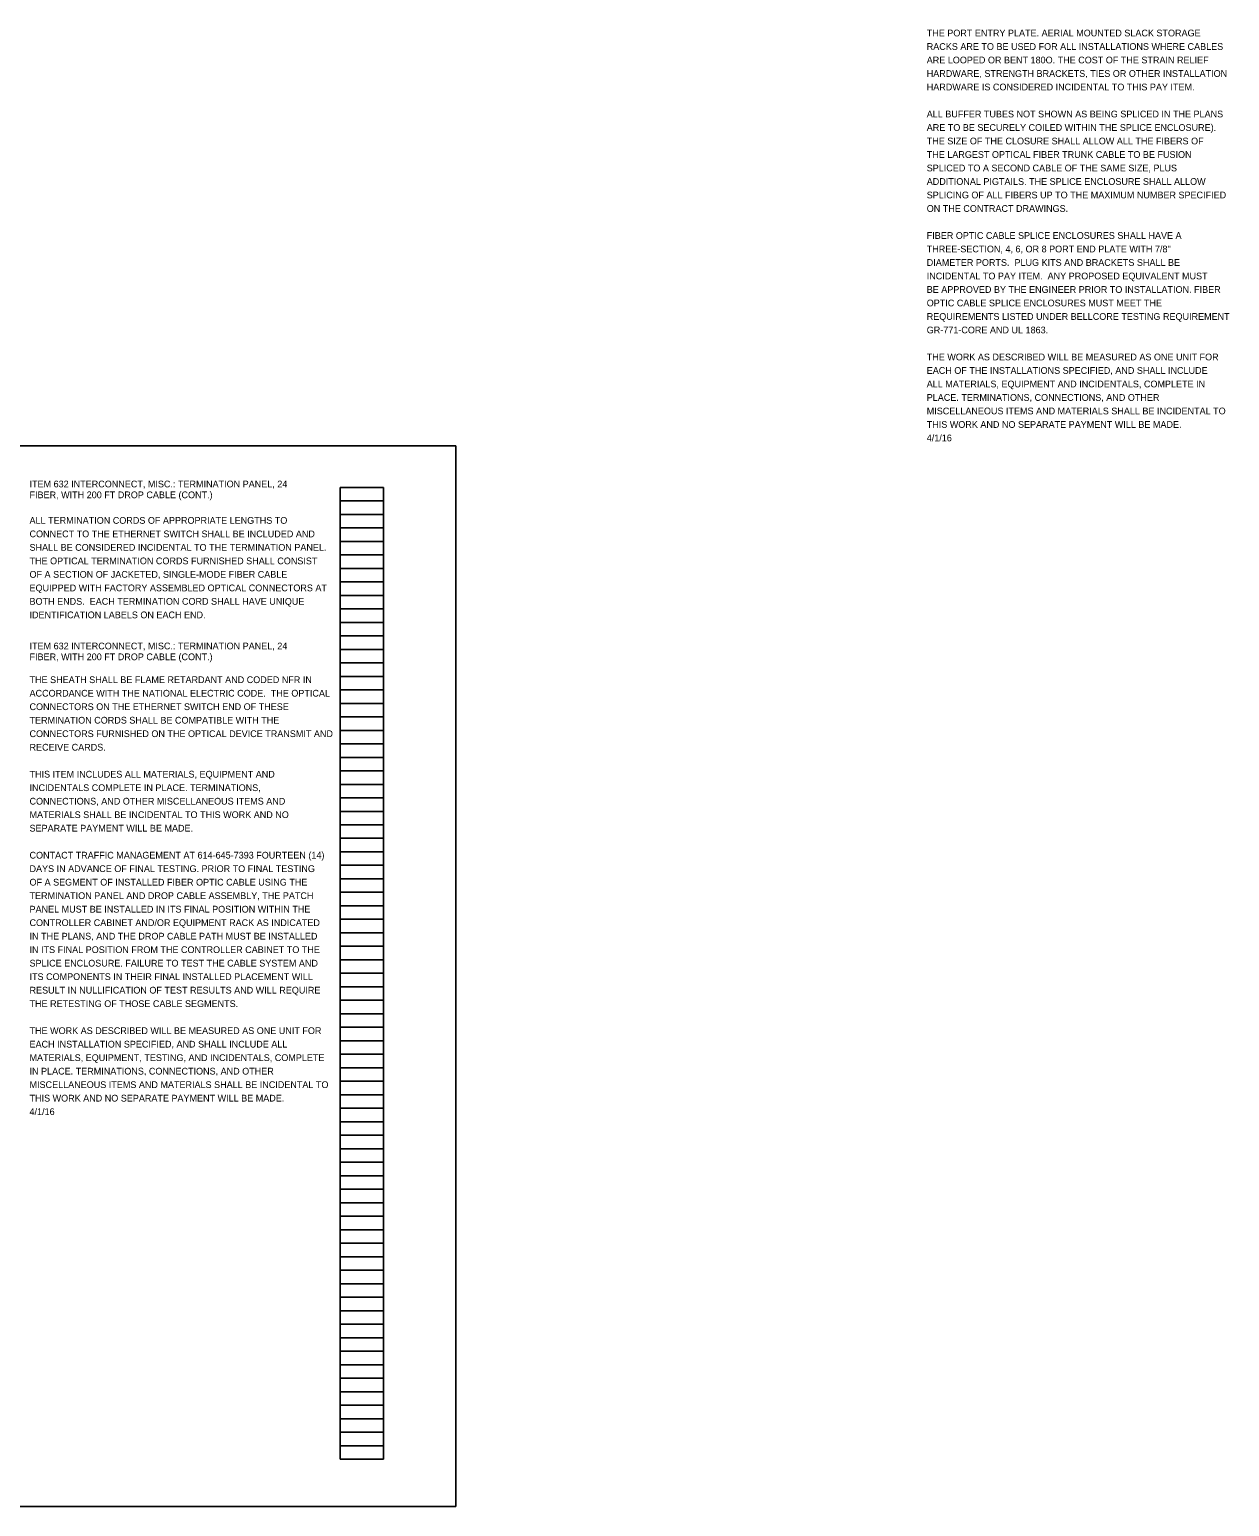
# Model space of a CAD drawing. Extents: x -36.9 to 49.6, y -47.1 to 37.
# Drawn here: x 24.65 to 49.54, y -47.06 to -16.43 of the extents above; entities that cross this region are included whole.
import ezdxf

# ---------------------------------------------------------------- set-up
doc = ezdxf.new("R2010")
doc.units = 0
for name, color, linetype in [('SC_Scratch1', 7, 'Continuous'), ('SH_Cut_Line', 7, 'Continuous'), ('SH_Data', 7, 'Continuous'), ('SH_Text', 7, 'Continuous')]:
    doc.layers.add(name, color=color, linetype=linetype)

msp = doc.modelspace()

# ---------------------------------------------------------------- linework, layer by layer
at = {"layer": 'SC_Scratch1'}
for p, q in [((31.094, -46.083), (31.094, -25.923)), ((31.094, -25.923), (31.994, -25.923)), ((31.994, -46.083), (31.994, -25.923)), ((31.094, -26.203), (31.994, -26.203)), ((31.094, -26.483), (31.994, -26.483)), ((31.094, -26.763), (31.994, -26.763)), ((31.094, -27.043), (31.994, -27.043)), ((31.094, -27.323), (31.994, -27.323)), ((31.094, -27.603), (31.994, -27.603)), ((31.094, -27.883), (31.994, -27.883)), ((31.094, -28.163), (31.994, -28.163)), ((31.094, -28.443), (31.994, -28.443)), ((31.094, -28.723), (31.994, -28.723)), ((31.094, -29.003), (31.994, -29.003)), ((31.094, -29.283), (31.994, -29.283)), ((31.094, -29.563), (31.994, -29.563)), ((31.094, -29.843), (31.994, -29.843)), ((31.094, -30.123), (31.994, -30.123)), ((31.094, -30.403), (31.994, -30.403)), ((31.094, -30.683), (31.994, -30.683)), ((31.094, -30.963), (31.994, -30.963)), ((31.094, -31.243), (31.994, -31.243)), ((31.094, -31.523), (31.994, -31.523)), ((31.094, -31.803), (31.994, -31.803)), ((31.094, -32.083), (31.994, -32.083)), ((31.094, -32.363), (31.994, -32.363)), ((31.094, -32.643), (31.994, -32.643)), ((31.094, -32.923), (31.994, -32.923)), ((31.094, -33.203), (31.994, -33.203)), ((31.094, -33.483), (31.994, -33.483)), ((31.094, -33.763), (31.994, -33.763)), ((31.094, -34.043), (31.994, -34.043)), ((31.094, -34.323), (31.994, -34.323)), ((31.094, -34.603), (31.994, -34.603)), ((31.094, -34.883), (31.994, -34.883)), ((31.094, -35.163), (31.994, -35.163)), ((31.094, -35.443), (31.994, -35.443)), ((31.094, -35.723), (31.994, -35.723)), ((31.094, -36.003), (31.994, -36.003)), ((31.094, -36.283), (31.994, -36.283)), ((31.094, -36.563), (31.994, -36.563)), ((31.094, -36.843), (31.994, -36.843)), ((31.094, -37.123), (31.994, -37.123)), ((31.094, -37.403), (31.994, -37.403)), ((31.094, -37.683), (31.994, -37.683)), ((31.094, -37.963), (31.994, -37.963)), ((31.094, -38.243), (31.994, -38.243)), ((31.094, -38.523), (31.994, -38.523)), ((31.094, -38.803), (31.994, -38.803)), ((31.094, -39.083), (31.994, -39.083)), ((31.094, -39.363), (31.994, -39.363)), ((31.094, -39.643), (31.994, -39.643)), ((31.094, -39.923), (31.994, -39.923)), ((31.094, -40.203), (31.994, -40.203)), ((31.094, -40.483), (31.994, -40.483)), ((31.094, -40.763), (31.994, -40.763)), ((31.094, -41.043), (31.994, -41.043)), ((31.094, -41.323), (31.994, -41.323)), ((31.094, -41.603), (31.994, -41.603)), ((31.094, -41.883), (31.994, -41.883)), ((31.094, -42.163), (31.994, -42.163)), ((31.094, -42.443), (31.994, -42.443)), ((31.094, -42.723), (31.994, -42.723)), ((31.094, -43.003), (31.994, -43.003)), ((31.094, -43.283), (31.994, -43.283)), ((31.094, -43.563), (31.994, -43.563)), ((31.094, -43.843), (31.994, -43.843)), ((31.094, -44.123), (31.994, -44.123)), ((31.094, -44.403), (31.994, -44.403)), ((31.094, -44.683), (31.994, -44.683)), ((31.094, -44.963), (31.994, -44.963)), ((31.094, -45.243), (31.994, -45.243)), ((31.094, -45.523), (31.994, -45.523)), ((31.094, -45.803), (31.994, -45.803)), ((31.094, -46.083), (31.994, -46.083))]:
    msp.add_line(p, q, dxfattribs=at)
at = {"layer": 'SH_Cut_Line'}
msp.add_lwpolyline([(-0.506, -47.063), (33.494, -47.063), (33.494, -25.063), (-0.506, -25.063)], close=True, dxfattribs=at)

# ---------------------------------------------------------------- texts
at = {"layer": 'SH_Data'}
for s, p in [('FIBER, WITH 200 FT DROP CABLE (CONT.)', (24.654, -26.148)), ('ITEM 632 INTERCONNECT, MISC.: TERMINATION PANEL, 24 ', (24.654, -25.923)), ('FIBER, WITH 200 FT DROP CABLE (CONT.)', (24.654, -29.508)), ('ITEM 632 INTERCONNECT, MISC.: TERMINATION PANEL, 24 ', (24.654, -29.283))]:
    msp.add_text(s, height=0.14, dxfattribs=at).set_placement(p)
at = {"layer": 'SH_Text'}
for s, p in [('THE PORT ENTRY PLATE. AERIAL MOUNTED SLACK STORAGE ', (43.262, -16.568)), ('RACKS ARE TO BE USED FOR ALL INSTALLATIONS WHERE CABLES ', (43.262, -16.848)), ('ARE LOOPED OR BENT 180O. THE COST OF THE STRAIN RELIEF ', (43.262, -17.128)), ('HARDWARE, STRENGTH BRACKETS, TIES OR OTHER INSTALLATION ', (43.262, -17.408)), ('HARDWARE IS CONSIDERED INCIDENTAL TO THIS PAY ITEM.', (43.262, -17.688)), ('ALL BUFFER TUBES NOT SHOWN AS BEING SPLICED IN THE PLANS ', (43.262, -18.248)), ('ARE TO BE SECURELY COILED WITHIN THE SPLICE ENCLOSURE).  ', (43.262, -18.528)), ('THE SIZE OF THE CLOSURE SHALL ALLOW ALL THE FIBERS OF ', (43.262, -18.808)), ('THE LARGEST OPTICAL FIBER TRUNK CABLE TO BE FUSION ', (43.262, -19.088)), ('SPLICED TO A SECOND CABLE OF THE SAME SIZE, PLUS ', (43.262, -19.368)), ('ADDITIONAL PIGTAILS. THE SPLICE ENCLOSURE SHALL ALLOW ', (43.262, -19.648)), ('SPLICING OF ALL FIBERS UP TO THE MAXIMUM NUMBER SPECIFIED ', (43.262, -19.928)), ('ON THE CONTRACT DRAWINGS.', (43.262, -20.208)), ('FIBER OPTIC CABLE SPLICE ENCLOSURES SHALL HAVE A ', (43.262, -20.768)), ('THREE-SECTION, 4, 6, OR 8 PORT END PLATE WITH 7/8" ', (43.262, -21.048)), ('DIAMETER PORTS.  PLUG KITS AND BRACKETS SHALL BE ', (43.262, -21.328)), ('BE APPROVED BY THE ENGINEER PRIOR TO INSTALLATION. FIBER ', (43.262, -21.888)), ('INCIDENTAL TO PAY ITEM.  ANY PROPOSED EQUIVALENT MUST ', (43.262, -21.608)), ('OPTIC CABLE SPLICE ENCLOSURES MUST MEET THE ', (43.262, -22.168)), ('REQUIREMENTS LISTED UNDER BELLCORE TESTING REQUIREMENT ', (43.262, -22.448)), ('GR-771-CORE AND UL 1863.', (43.262, -22.728)), ('THE WORK AS DESCRIBED WILL BE MEASURED AS ONE UNIT FOR ', (43.262, -23.288)), ('EACH OF THE INSTALLATIONS SPECIFIED, AND SHALL INCLUDE ', (43.262, -23.568)), ('ALL MATERIALS, EQUIPMENT AND INCIDENTALS, COMPLETE IN ', (43.262, -23.848)), ('PLACE. TERMINATIONS, CONNECTIONS, AND OTHER ', (43.262, -24.128)), ('MISCELLANEOUS ITEMS AND MATERIALS SHALL BE INCIDENTAL TO ', (43.262, -24.408)), ('THIS WORK AND NO SEPARATE PAYMENT WILL BE MADE.', (43.262, -24.688)), ('4/1/16', (43.262, -24.968)), ('ALL TERMINATION CORDS OF APPROPRIATE LENGTHS TO ', (24.654, -26.678)), ('CONNECT TO THE ETHERNET SWITCH SHALL BE INCLUDED AND ', (24.654, -26.958)), ('SHALL BE CONSIDERED INCIDENTAL TO THE TERMINATION PANEL.  ', (24.654, -27.238)), ('THE OPTICAL TERMINATION CORDS FURNISHED SHALL CONSIST ', (24.654, -27.518)), ('OF A SECTION OF JACKETED, SINGLE-MODE FIBER CABLE ', (24.654, -27.798)), ('EQUIPPED WITH FACTORY ASSEMBLED OPTICAL CONNECTORS AT ', (24.654, -28.078)), ('BOTH ENDS.  EACH TERMINATION CORD SHALL HAVE UNIQUE ', (24.654, -28.358)), ('IDENTIFICATION LABELS ON EACH END.', (24.654, -28.638)), ('THE SHEATH SHALL BE FLAME RETARDANT AND CODED NFR IN ', (24.654, -29.983)), ('ACCORDANCE WITH THE NATIONAL ELECTRIC CODE.  THE OPTICAL ', (24.654, -30.263)), ('CONNECTORS ON THE ETHERNET SWITCH END OF THESE ', (24.654, -30.543)), ('TERMINATION CORDS SHALL BE COMPATIBLE WITH THE ', (24.654, -30.823)), ('CONNECTORS FURNISHED ON THE OPTICAL DEVICE TRANSMIT AND ', (24.654, -31.103)), ('RECEIVE CARDS.', (24.654, -31.383)), ('THIS ITEM INCLUDES ALL MATERIALS, EQUIPMENT AND ', (24.654, -31.943)), ('INCIDENTALS COMPLETE IN PLACE. TERMINATIONS, ', (24.654, -32.223)), ('CONNECTIONS, AND OTHER MISCELLANEOUS ITEMS AND ', (24.654, -32.503)), ('MATERIALS SHALL BE INCIDENTAL TO THIS WORK AND NO ', (24.654, -32.783)), ('SEPARATE PAYMENT WILL BE MADE.', (24.654, -33.063)), ('CONTACT TRAFFIC MANAGEMENT AT 614-645-7393 FOURTEEN (14) ', (24.654, -33.623)), ('DAYS IN ADVANCE OF FINAL TESTING. PRIOR TO FINAL TESTING ', (24.654, -33.903)), ('OF A SEGMENT OF INSTALLED FIBER OPTIC CABLE USING THE ', (24.654, -34.183)), ('TERMINATION PANEL AND DROP CABLE ASSEMBLY, THE PATCH ', (24.654, -34.463)), ('PANEL MUST BE INSTALLED IN ITS FINAL POSITION WITHIN THE ', (24.654, -34.743)), ('CONTROLLER CABINET AND/OR EQUIPMENT RACK AS INDICATED ', (24.654, -35.023)), ('IN THE PLANS, AND THE DROP CABLE PATH MUST BE INSTALLED ', (24.654, -35.303)), ('IN ITS FINAL POSITION FROM THE CONTROLLER CABINET TO THE ', (24.654, -35.583)), ('SPLICE ENCLOSURE. FAILURE TO TEST THE CABLE SYSTEM AND ', (24.654, -35.863)), ('ITS COMPONENTS IN THEIR FINAL INSTALLED PLACEMENT WILL ', (24.654, -36.143)), ('RESULT IN NULLIFICATION OF TEST RESULTS AND WILL REQUIRE ', (24.654, -36.423)), ('THE RETESTING OF THOSE CABLE SEGMENTS.                                       ', (24.654, -36.703)), ('THE WORK AS DESCRIBED WILL BE MEASURED AS ONE UNIT FOR ', (24.654, -37.263)), ('EACH INSTALLATION SPECIFIED, AND SHALL INCLUDE ALL ', (24.654, -37.543)), ('MATERIALS, EQUIPMENT, TESTING, AND INCIDENTALS, COMPLETE ', (24.654, -37.823)), ('IN PLACE. TERMINATIONS, CONNECTIONS, AND OTHER ', (24.654, -38.103)), ('MISCELLANEOUS ITEMS AND MATERIALS SHALL BE INCIDENTAL TO ', (24.654, -38.383)), ('THIS WORK AND NO SEPARATE PAYMENT WILL BE MADE. ', (24.654, -38.663)), ('4/1/16', (24.654, -38.943))]:
    msp.add_text(s, height=0.14, dxfattribs=at).set_placement(p)

doc.saveas('drawing.dxf')
